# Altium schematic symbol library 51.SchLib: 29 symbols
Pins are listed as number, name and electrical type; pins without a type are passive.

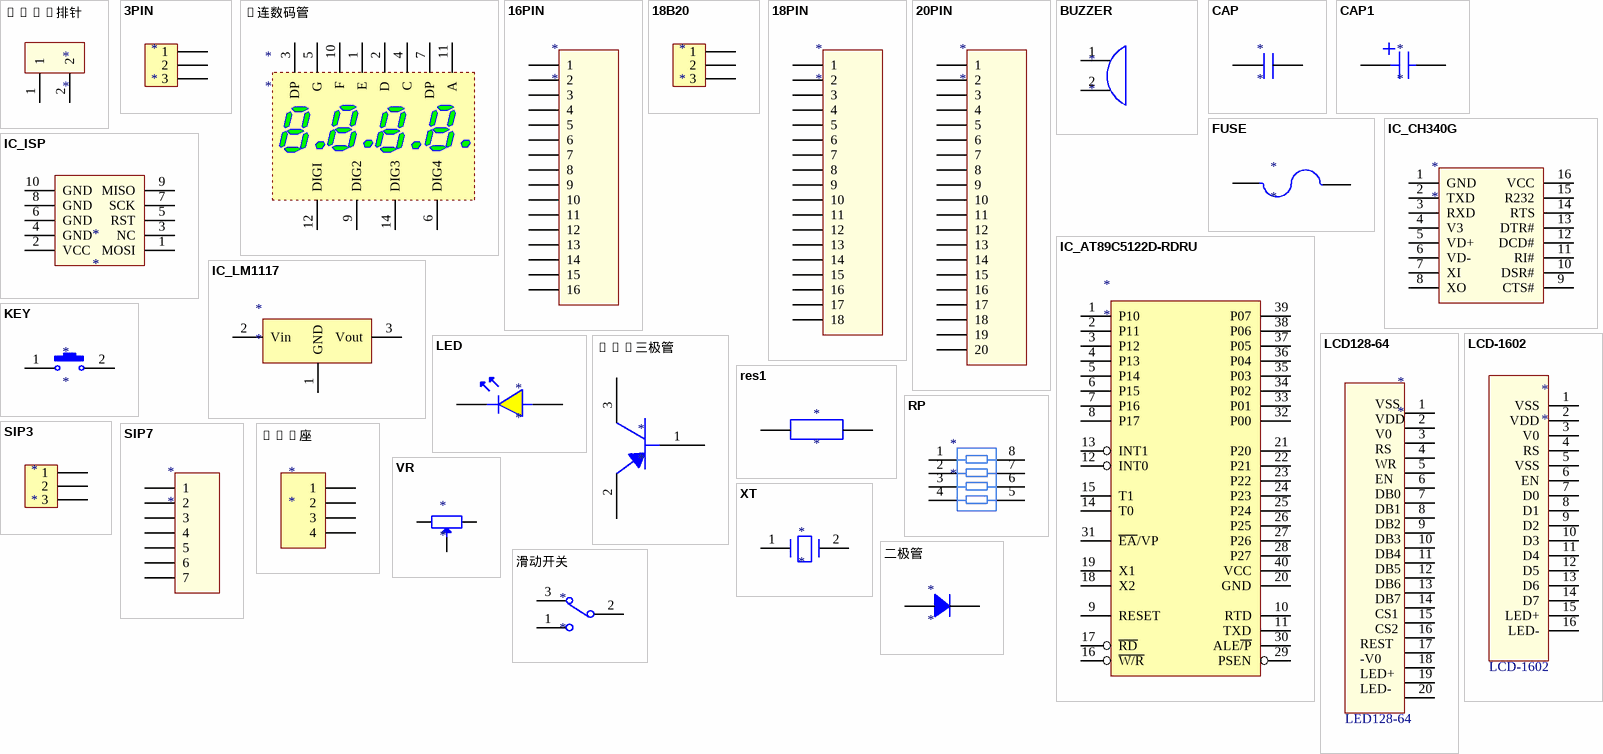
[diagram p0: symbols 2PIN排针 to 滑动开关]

## 2PIN排针
designator *
footprint HDR1X2 (Connector; Header; 2 Position)
pins: 1, 2

## 3PIN
designator *
footprint HDR1X3 (Connector; Header; 3 Position)
pins: 1, 2, 3

## 4连数码管
designator *
footprint 1206F
footprint 3416BS
pins: 1 E, 2 D, 3 DP, 4 C, 5 G, 6 DIG4, 7 DP, 9 DIG2, 10 F, 11 A, 12 DIGI, 14 DIG3

## 16PIN
designator *
footprint HDR1X16 (ZLGLIB)
pins: 1, 2, 3, 4, 5, 6, 7, 8, 9, 10, 11, 12, 13, 14, 15, 16

## 18B20
designator *
footprint HDR1X3 (Connector; Header; 3 Position)
pins: 1, 2, 3

## 18PIN
designator *
footprint HDR1X18 (ZLGLIB)
pins: 1, 2, 3, 4, 5, 6, 7, 8, 9, 10, 11, 12, 13, 14, 15, 16, 17, 18

## 20PIN
designator *
footprint HDR1X20 (Connector; Header; 20 Position)
pins: 1, 2, 3, 4, 5, 6, 7, 8, 9, 10, 11, 12, 13, 14, 15, 16, 17, 18, 19, 20

## BUZZER
designator *
footprint BUZZER
pins: 1, 2

## CAP
designator *
footprint FPC-0402C
pins: 1, 2

## CAP1
designator *
footprint FPC-CPCSM-3R2X8R0-1
pins: 1, 2

## FUSE
designator *
footprint 1206F
pins: 1, 2

## IC_AT89C5122D-RDRU
designator *
footprint DIP40
pins: 1 P10, 2 P11, 3 P12, 4 P13, 5 P14, 6 P15, 7 P16, 8 P17, 9 RESET, 10 RTD, 11 TXD, 12 INT0, 13 INT1, 14 T0, 15 T1, 16 ~{W}~{/R}, 17 ~{RD}, 18 X2, 19 X1, 20 GND, 21 P20, 22 P21, 23 P22, 24 P23, 25 P24, 26 P25, 27 P26, 28 P27, 29 PSEN, 30 ALE~{/P}, 31 ~{EA}/VP, 32 P00, 33 P01, 34 P02, 35 P03, 36 P04, 37 P05, 38 P06, 39 P07, 40 VCC

## IC_CH340G
designator *
footprint FPC-SO16-150
pins: 1 GND, 2 TXD, 3 RXD, 4 V3, 5 VD+, 6 VD-, 7 XI, 8 XO, 9 CTS#, 10 DSR#, 11 RI#, 12 DCD#, 13 DTR#, 14 RTS, 15 R232, 16 VCC

## IC_ISP
designator *
footprint FPC-CON20VS2R00-2X5TM-1
pins: 1 MOSI, 2 VCC, 3 NC, 4 GND, 5 RST, 6 GND, 7 SCK, 8 GND, 9 MISO, 10 GND

## IC_LM1117
designator *
footprint FPC-SOT323
footprint SOP-223-3L
pins: 1 GND, 2 Vin, 3 Vout

## KEY
designator *
footprint SW-PB
pins: 1, 2

## LCD128-64
designator *
footprint HDR1X20 (Connector; Header; 20 Position)
pins: 1 VSS, 2 VDD, 3 V0, 4 RS, 5 WR, 6 EN, 7 DB0, 8 DB1, 9 DB2, 10 DB3, 11 DB4, 12 DB5, 13 DB6, 14 DB7, 15 CS1, 16 CS2, 17 REST, 18 -V0, 19 LED+, 20 LED-

## LCD-1602
designator *
footprint HDR1X16 (ZLGLIB)
pins: 1 VSS, 2 VDD, 3 V0, 4 RS, 5 VSS, 6 EN, 7 D0, 8 D1, 9 D2, 10 D3, 11 D4, 12 D5, 13 D6, 14 D7, 15 LED+, 16 LED-

## LED
designator *
footprint LED0805 (Footprint not found)
footprint FPC-0805D
pins: 1, 2

## PNP三极管
designator *
footprint FPC-SOT323
pins: 1, 2, 3

## res1
designator *
footprint FPC-0402R
pins: 1, 2

## RP
designator *
footprint RP0603 (Footprint not found)
footprint FPC-0603RA
pins: 1, 2, 3, 4, 5, 6, 7, 8

## SIP3
designator *
footprint HDR1X3 (Connector; Header; 3 Position)
pins: 1, 2, 3

## SIP7
designator *
footprint HDR1X7 (Connector; Header; 7 Position)
pins: 1, 2, 3, 4, 5, 6, 7

## USB座
designator *
footprint usb-a (2)
pins: 1, 2, 3, 4

## VR
designator *
footprint RV
pins: 1, 2, 3

## XT
designator *
footprint FPC-CO2-5R0X11R5-V
pins: 1, 2

## 二极管
designator *
footprint FPC-1206D
pins: 1, 2

## 滑动开关
designator *
footprint SS-12F44
pins: 1, 2, 3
